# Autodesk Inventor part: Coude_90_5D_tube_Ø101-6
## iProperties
Shininess: 64.0
Length Units: 11269
Angle Units: 11279
Time Units: 11290
Mass Units: 11283
Length Display Precision: 3
Angle Display Precision: 2
Compacted: True
Part Number: Coude_90_5D_tube_Ø101-6
Document SubType Name: Modeling
Created: 2008-04
Material: Par défaut
Designer: plup
Density: 0.0
Volumn: 0.0
Area: 0.0
PropertySet Name: Model Information
Control State: 0
Master: False
Checked Out: False
MATIERE_PIECE: X2CrNi 18-11
DESIGNATION: Coude DN 100 90° 5D
Author: plup
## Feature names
1. Balayage1
